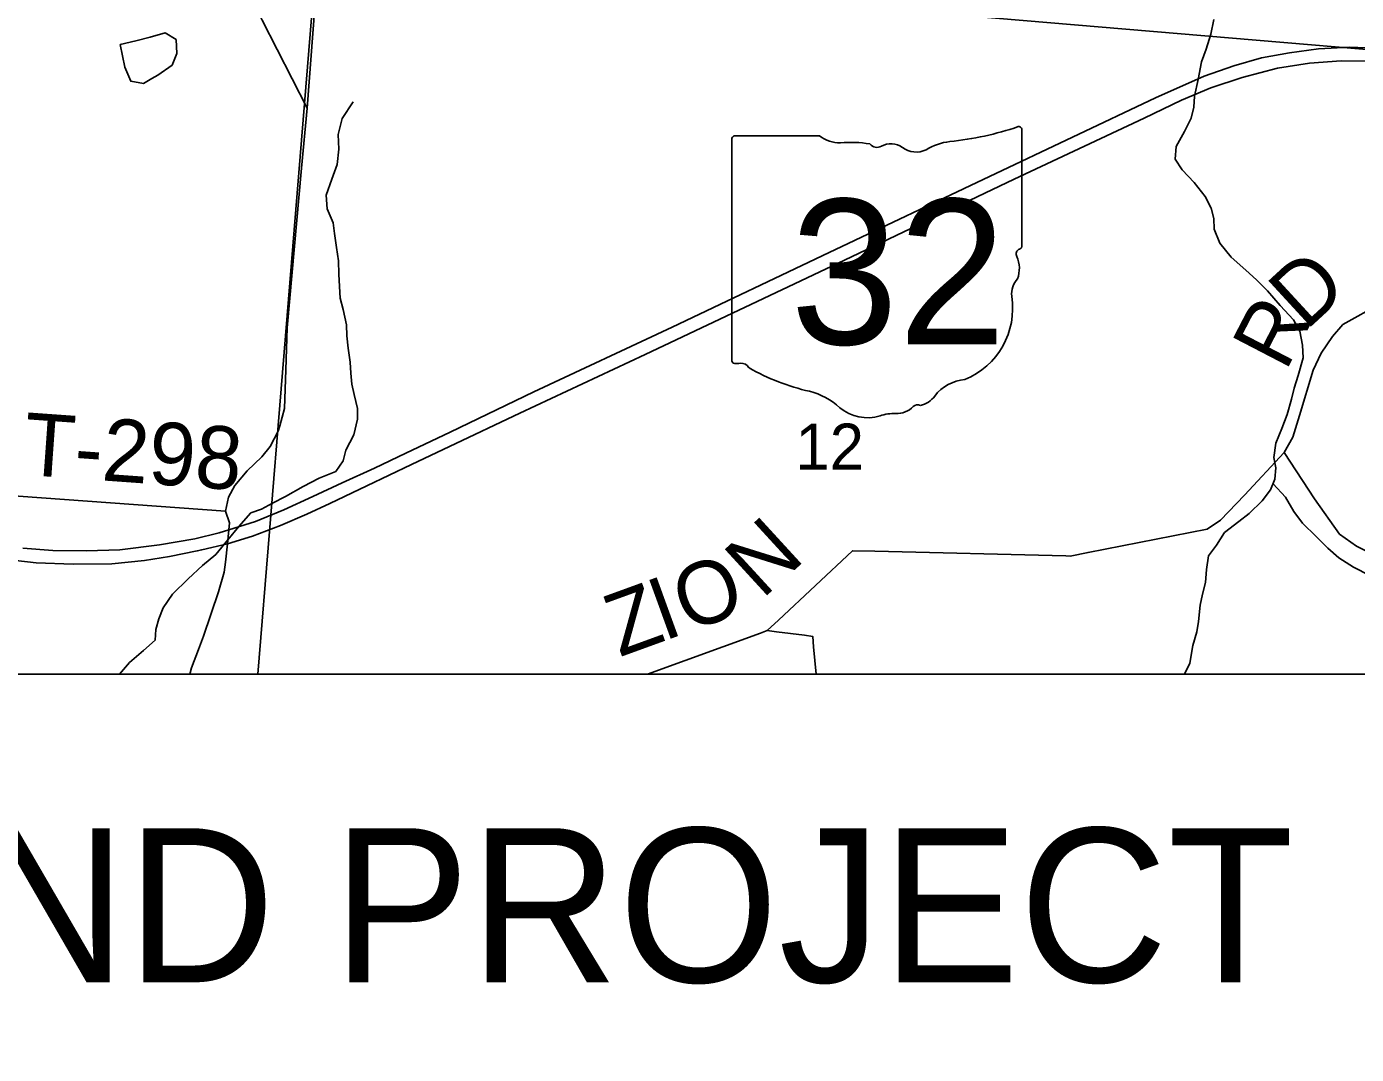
# Model space of a CAD drawing. Extents: x 0 to 34, y 0 to 22.
# Drawn here: x 24.965 to 26.174, y 18.118 to 19.052 of the extents above; entities that cross this region are included whole.
import ezdxf

# ---------------------------------------------------------------- set-up
doc = ezdxf.new("R2010")
doc.units = 0
for name, color, linetype in [('GM_X_Corporation', 7, 'Continuous'), ('GM_X_County_Road', 7, 'Continuous'), ('GM_X_County_Road_Text', 7, 'Continuous'), ('GM_X_Minor_Lake', 7, 'Continuous'), ('GM_X_Minor_River', 7, 'Continuous'), ('GM_X_Section_Text', 7, 'Continuous'), ('GM_X_State_Location', 7, 'Continuous'), ('GM_X_State_Route', 7, 'Continuous'), ('GM_X_State_Shield', 7, 'Continuous'), ('GM_X_Township_Road', 7, 'Continuous'), ('GM_X_Township_Road_Text', 7, 'Continuous'), ('SH_Data', 7, 'Continuous'), ('SH_Text', 7, 'Continuous')]:
    doc.layers.add(name, color=color, linetype=linetype)

msp = doc.modelspace()

# ---------------------------------------------------------------- linework, layer by layer
at = {"layer": 'GM_X_Corporation'}
msp.add_lwpolyline([(26.302, 19.9328), (26.2267, 19.0272), (25.2286, 19.1118), (25.2979, 20.0049)], close=True, dxfattribs=at)
for points in [[(24.656, 18.1575), (24.0929, 18.2038), (24.145, 19.219), (25.2286, 19.1118), (25.1756, 18.4635)], [(25.1756, 18.4635), (25.2286, 19.1118), (26.2267, 19.0272), (26.2169, 18.8995), (26.1832, 18.4635)]]:
    msp.add_lwpolyline(points, dxfattribs=at)
at = {"layer": 'GM_X_County_Road'}
for points in [[(25.1954, 18.6891), (25.1997, 18.7047), (25.201, 18.7398), (25.2023, 18.7782), (25.2153, 18.9232), (25.2205, 18.9776), (25.2517, 19.3889), (25.2535, 19.4025)], [(25.5296, 18.4635), (25.6325, 18.5008), (25.6385, 18.503), (25.6487, 18.5126), (25.7159, 18.5755), (25.7363, 18.5751), (25.9101, 18.5708), (25.9139, 18.5707), (25.9301, 18.5741), (26.0384, 18.5952), (26.0505, 18.6033), (26.0725, 18.6261), (26.1085, 18.6647), (26.1162, 18.6788), (26.1224, 18.6983), (26.1347, 18.7397), (26.1421, 18.755), (26.1524, 18.7703), (26.1618, 18.7812), (26.1967, 18.8005)], [(25.1217, 18.4858), (25.1262, 18.4978), (25.1397, 18.5381), (25.1449, 18.5561), (25.146, 18.5652), (25.1479, 18.5819), (25.1491, 18.5946), (25.1497, 18.601), (25.146, 18.6116), (25.149, 18.6242), (25.1546, 18.6348), (25.1659, 18.6481), (25.1791, 18.661), (25.1868, 18.6702), (25.194, 18.6842), (25.1954, 18.6891)], [(25.1137, 18.4635), (25.1153, 18.4691), (25.1217, 18.4858)]]:
    msp.add_lwpolyline(points, dxfattribs=at)
at = {"layer": 'GM_X_Minor_Lake'}
for points in [[(25.0792, 19.0046), (25.0846, 19.0077), (25.0978, 19.0168), (25.102, 19.0274), (25.1012, 19.0399), (25.0914, 19.046), (25.0778, 19.0422), (25.0645, 19.0388), (25.0505, 19.0354)], [(25.0505, 19.0354), (25.0547, 19.015), (25.06, 19.0021), (25.0717, 19.0001), (25.0792, 19.0046)]]:
    msp.add_lwpolyline(points, dxfattribs=at)
at = {"layer": 'GM_X_Minor_River'}
for points in [[(26.0445, 19.0582), (26.0418, 19.0449), (26.0375, 19.0313), (26.0333, 19.0196), (26.0302, 19.0037), (26.027, 18.9885), (26.0262, 18.9787), (26.0239, 18.9685), (26.0177, 18.9564), (26.0101, 18.9428), (26.0092, 18.9314), (26.0156, 18.9215), (26.0265, 18.91), (26.0366, 18.8975), (26.0422, 18.8868), (26.0444, 18.8773), (26.0448, 18.8678), (26.05, 18.8549), (26.0601, 18.8423), (26.0736, 18.8305), (26.0834, 18.8217), (26.0932, 18.8117), (26.1048, 18.7984), (26.1168, 18.7854), (26.1225, 18.7751), (26.125, 18.7622), (26.1257, 18.7508), (26.121, 18.7349), (26.1176, 18.7232), (26.1152, 18.7134), (26.111, 18.6994), (26.1063, 18.6865), (26.1009, 18.6733), (26.099, 18.6604), (26.1008, 18.6509), (26.1, 18.6407), (26.0961, 18.6308), (26.0885, 18.621), (26.0767, 18.6093), (26.0672, 18.6022), (26.0542, 18.592), (26.047, 18.5807), (26.0397, 18.5709), (26.0377, 18.5584), (26.0369, 18.5466), (26.0342, 18.536), (26.0322, 18.5262), (26.0306, 18.5114), (26.029, 18.5019), (26.0255, 18.4894), (26.0228, 18.4735), (26.0177, 18.4635)], [(25.0499, 18.4635), (25.059, 18.4741), (25.0716, 18.485), (25.0822, 18.4944), (25.0827, 18.5039), (25.0854, 18.5138), (25.0896, 18.5236), (25.098, 18.5361), (25.1121, 18.55), (25.1251, 18.562), (25.1373, 18.5722), (25.1483, 18.5854), (25.1582, 18.5975), (25.1693, 18.6099), (25.1788, 18.6133), (25.189, 18.6189), (25.2008, 18.6249), (25.2168, 18.6339), (25.2312, 18.6414), (25.2464, 18.6474), (25.2532, 18.6572), (25.2556, 18.667), (25.2629, 18.681), (25.266, 18.695), (25.2661, 18.7049), (25.2631, 18.7174), (25.2609, 18.7269), (25.2602, 18.7368), (25.2595, 18.747), (25.2577, 18.7595), (25.2563, 18.7709), (25.256, 18.7808), (25.253, 18.7948), (25.2505, 18.8051), (25.2498, 18.8157), (25.2491, 18.8267), (25.2488, 18.8389), (25.247, 18.851), (25.2452, 18.8639), (25.2441, 18.8734), (25.2385, 18.8863), (25.2375, 18.8985), (25.2429, 18.9132), (25.2475, 18.9265), (25.2491, 18.9405), (25.2485, 18.9538), (25.2523, 18.9682), (25.2623, 18.9833)], [(26.0983, 18.6363), (26.1097, 18.6243), (26.1172, 18.6113), (26.125, 18.6007), (26.1375, 18.5884), (26.148, 18.5778), (26.1581, 18.569), (26.1713, 18.5605), (26.1864, 18.5532)]]:
    msp.add_lwpolyline(points, dxfattribs=at)
at = {"layer": 'GM_X_State_Route'}
for points in [[(24.9619, 18.578), (24.9891, 18.5758), (25.0198, 18.5755), (25.05, 18.5765), (25.0861, 18.5808), (25.1184, 18.5865), (25.1404, 18.5919), (25.1491, 18.5946), (25.1733, 18.6021), (25.1993, 18.6127), (25.2256, 18.6248), (25.2523, 18.6372), (25.2816, 18.6505), (25.3099, 18.6643), (25.3503, 18.6834), (25.4265, 18.7199), (25.552, 18.7786), (25.6949, 18.8464), (25.8405, 18.9155), (25.9915, 18.9869), (26.0356, 19.0066), (26.0628, 19.016), (26.0878, 19.0234), (26.1133, 19.028), (26.1396, 19.0315), (26.168, 19.033), (26.1973, 19.0318)], [(25.3496, 18.6702), (25.4138, 18.7006), (25.5277, 18.7538), (25.7087, 18.8396), (25.8629, 18.913), (25.981, 18.9686), (26.0152, 18.985), (26.0417, 18.9962), (26.0701, 19.0054), (26.1024, 19.014), (26.1315, 19.0186), (26.1601, 19.0207), (26.1899, 19.0202), (26.2273, 19.0163), (26.2503, 19.012), (26.2766, 19.0051), (26.3063, 18.9944), (26.3317, 18.9829), (26.3654, 18.9656), (26.4009, 18.9463)], [(24.5182, 18.8324), (24.5974, 18.7646), (24.6811, 18.6934), (24.7147, 18.6656), (24.7456, 18.6432), (24.7675, 18.6299), (24.7968, 18.6139), (24.8254, 18.6009), (24.8504, 18.5914), (24.8813, 18.5815), (24.9113, 18.5741), (24.945, 18.568), (24.9739, 18.5647), (25.0076, 18.5634), (25.0428, 18.5638), (25.0725, 18.5666), (25.0952, 18.5702), (25.1205, 18.5754), (25.1245, 18.5764), (25.1479, 18.5819)], [(25.1479, 18.5819), (25.1708, 18.5888), (25.1962, 18.5986), (25.2202, 18.6088), (25.2411, 18.6185), (25.2746, 18.6345), (25.3153, 18.6539), (25.3496, 18.6702)]]:
    msp.add_lwpolyline(points, dxfattribs=at)
at = {"layer": 'GM_X_State_Shield'}
for p, q in [((25.87, 18.8529), (25.87, 18.9575)), ((25.6063, 18.9491), (25.6063, 18.749)), ((25.6861, 18.9526), (25.6089, 18.9526)), ((25.87, 18.8529), (25.87, 18.8529))]:
    msp.add_line(p, q, dxfattribs=at)
for centre, radius, start, end in [((25.7761, 19.2254), 0.2796, 275.8445, 288.9065), ((25.8671, 18.958), 0.00294, 351.8621, 97.738), ((25.6093, 18.9496), 0.00305, 98.1301, 188.1301), ((25.7045, 18.9758), 0.0296, 231.6195, 271.1119), ((25.7143, 18.8402), 0.1064, 80.4867, 94.9883), ((25.7385, 18.9506), 0.00855, 219.7921, 297.1024), ((25.751, 18.9275), 0.0178, 54.4667, 119.1411), ((25.774, 18.9592), 0.0214, 233.8562, 294.8282), ((25.8117, 18.8915), 0.0563, 97.3462, 120.7689), ((25.8693, 18.8452), 0.00454, 107.944, 210.337), ((25.8669, 18.8525), 0.00314, 289.6038, 7.7341), ((25.8404, 18.8319), 0.0273, 340.033, 23.6496), ((25.8805, 18.8091), 0.0198, 136.8065, 186.9296), ((25.7917, 18.7957), 0.0699, 292.3089, 8.9858), ((25.6094, 18.7486), 0.00308, 171.9584, 258.3066), ((25.6098, 18.7691), 0.0235, 267.339, 280.6039), ((25.6146, 18.7375), 0.00848, 29.7484, 93.2717), ((25.7217, 18.9173), 0.2019, 240.4129, 257.1985), ((25.8212, 18.6928), 0.0383, 94.4031, 142.5768), ((25.6615, 18.6591), 0.0632, 47.1842, 75.836), ((25.7727, 18.7296), 0.0226, 282.8732, 323.2771), ((25.7298, 18.7365), 0.0401, 230.7004, 286.2918), ((25.753, 18.6673), 0.0329, 85.6951, 111.2099), ((25.7559, 18.7215), 0.0214, 268.777, 315.5493), ((25.7753, 18.7021), 0.00601, 65.7517, 132.6484)]:
    msp.add_arc(centre, radius, start, end, dxfattribs=at)
at = {"layer": 'GM_X_Township_Road'}
for points in [[(25.015, 19.0796), (25.1282, 19.0895), (25.1339, 19.0897), (25.1402, 19.0891), (25.1449, 19.0881), (25.1495, 19.0867), (25.1532, 19.0853), (25.1564, 19.0838), (25.1598, 19.0817), (25.1647, 19.078), (25.1679, 19.075), (25.1707, 19.072), (25.1732, 19.0687), (25.1762, 19.0644), (25.1794, 19.0575), (25.2205, 18.9776)], [(24.5333, 18.8632), (24.5426, 18.8551), (24.5554, 18.8406), (24.5768, 18.8239), (24.5938, 18.8124), (24.6135, 18.8018), (24.6612, 18.7672), (24.6881, 18.7463), (24.8963, 18.6356), (24.9152, 18.6286), (24.9369, 18.6265), (25.146, 18.6116)], [(26.2609, 18.5685), (26.2519, 18.568), (26.2052, 18.5687), (26.1928, 18.5702), (26.174, 18.5797), (26.1588, 18.5907), (26.136, 18.6227), (26.1085, 18.6647)], [(25.6385, 18.503), (25.6469, 18.5019), (25.6724, 18.4987), (25.6799, 18.4977), (25.6807, 18.4882), (25.683, 18.4635)]]:
    msp.add_lwpolyline(points, dxfattribs=at)
at = {"layer": 'SH_Data'}
msp.add_lwpolyline([(24.656, 18.4635), (26.3421, 18.4635), (26.3421, 17.6235), (24.656, 17.6235)], close=True, dxfattribs=at)

# ---------------------------------------------------------------- texts
at = {"layer": 'GM_X_County_Road_Text'}
for s, rotation, p in [('D', 42.6295, (26.128, 18.7748)), ('R', 62.5814, (26.1097, 18.7375)), ('N', 42.5255, (25.6338, 18.5308)), ('O', 19.9603, (25.5659, 18.5011)), ('Z', 19.9604, (25.5043, 18.4787)), ('I', 19.9603, (25.5442, 18.4932))]:
    msp.add_text(s, height=0.0568, rotation=rotation, dxfattribs=at).set_placement(p)
at = {"layer": 'GM_X_Section_Text'}
msp.add_text('12', height=0.04186, rotation=0, dxfattribs=at).set_placement((25.6642, 18.6492))
at = {"layer": 'GM_X_State_Location'}
for s in ['s', 'r']:
    msp.add_text(s, height=0.000189, dxfattribs=at).set_placement((25.7352, 18.8358))
msp.add_text('32', height=0.000189, rotation=0, dxfattribs=at).set_placement((25.6875, 18.822))
at = {"layer": 'GM_X_State_Shield'}
msp.add_text('32', height=0.13184, dxfattribs=at).set_placement((25.6595, 18.7631))
at = {"layer": 'GM_X_Township_Road_Text'}
msp.add_text('T-298', height=0.05682, rotation=355.9278, dxfattribs=at).set_placement((24.9612, 18.6446))
at = {"layer": 'SH_Text'}
msp.add_text('END PROJECT', height=0.14, dxfattribs=at).set_placement((24.796, 18.1835))

doc.saveas('drawing.dxf')
